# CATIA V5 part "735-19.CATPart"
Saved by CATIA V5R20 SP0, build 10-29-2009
Part number: 735-19
Bounding box of the stored display mesh (mm): x -20 to 20, y -20 to 20, z -23 to 20
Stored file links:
  C:\Users\Utente\Desktop\IO LAVORO\3D X SITO CF\X SITO\735\735-19.CATPart
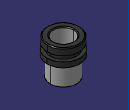
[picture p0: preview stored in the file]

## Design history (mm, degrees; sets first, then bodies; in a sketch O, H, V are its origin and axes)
Set1
  DatumSurface1 to DatumSurface25 "735-19"
Body1 (main body)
